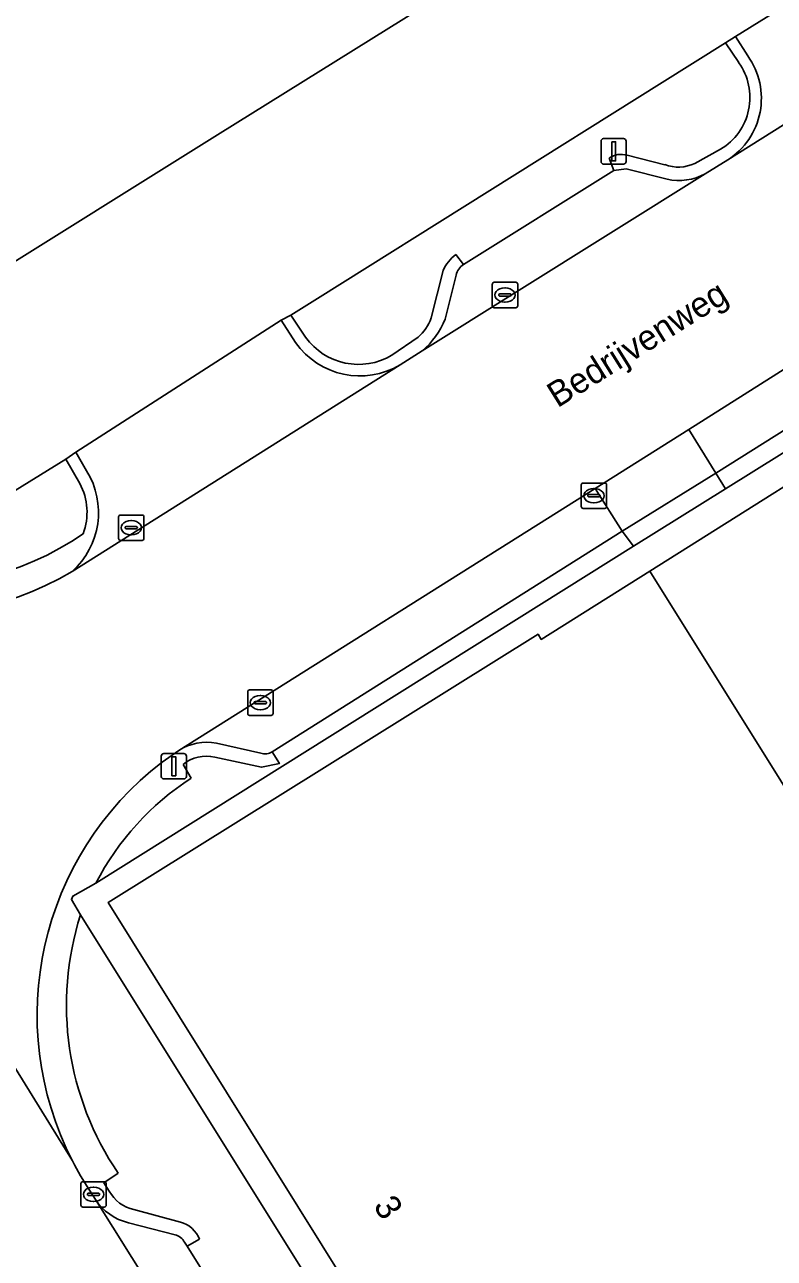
# Model space of a CAD drawing. Extents: x 158455 to 159797, y 387218 to 388672.
# Drawn here: x 158669.4 to 158698.98, y 387821.12 to 387869.77 of the extents above; entities that cross this region are included whole.
import ezdxf

# ---------------------------------------------------------------- set-up
doc = ezdxf.new("R2010")
doc.units = 0
for name, color, linetype in [('IMGEO_Erf', 7, 'Continuous'), ('IMGEO_Kolk', 7, 'Continuous'), ('IMGEO_Lichtmast', 7, 'Continuous'), ('IMGEO_Openbare_ruimte_label', 7, 'Continuous'), ('IMGEO_Pand', 7, 'Continuous'), ('IMGEO_Pand_nummerreeks', 7, 'Continuous'), ('IMGEO_Parkeervlak_open', 7, 'Continuous'), ('IMGEO_Rijbaan_lokaal_gesloten', 7, 'Continuous'), ('IMGEO_Voetpad_open', 7, 'Continuous')]:
    doc.layers.add(name, color=color, linetype=linetype)

msp = doc.modelspace()

# ---------------------------------------------------------------- linework, layer by layer
at = {"layer": 'IMGEO_Erf'}
for points in [[(158744.632, 387907.644), (158716.744, 387890.253), (158714.098, 387894.495), (158687.775, 387878.041), (158690.425, 387873.793), (158677.015, 387865.43), (158667.384, 387859.424), (158662.454, 387856.35), (158644.272, 387885.505), (158643.854, 387886.176), (158641.521, 387884.673), (158641.96, 387883.947), (158641.155, 387883.425), (158643.018, 387880.44), (158642.777, 387880.261), (158649.526, 387869.562), (158649.764, 387869.704), (158660.427, 387852.506)], [(158667.843, 387850.68), (158671.035, 387852.64), (158671.42, 387852.913), (158679.517, 387858.122), (158679.905, 387858.319), (158680.956, 387858.977), (158694.549, 387867.497), (158697.049, 387869.064), (158697.447, 387869.303), (158720.745, 387883.755), (158721.126, 387883.994), (158737.622, 387894.417), (158738.014, 387894.663), (158743.631, 387898.186), (158744.037, 387898.407), (158746.473, 387899.899)], [(158707.009, 387857.672), (158697.055, 387851.465), (158693.417, 387849.212), (158672.211, 387835.913), (158671.304, 387835.407), (158671.246, 387835.269), (158671.606, 387834.665), (158691.111, 387803.48), (158696.218, 387795.316), (158699.252, 387790.473), (158714.054, 387766.818), (158717.252, 387761.719), (158733.714, 387772.034), (158739.37, 387775.529), (158743.923, 387778.371), (158747.2, 387780.372), (158755.504, 387785.603)]]:
    msp.add_lwpolyline(points, dxfattribs=at)
msp.add_lwpolyline([(158694.061, 387848.221), (158704.182, 387854.586), (158709.488, 387846.148), (158713.329, 387848.544), (158722.022, 387834.609), (158708.006, 387825.866), (158703.715, 387823.19), (158703.941, 387822.828), (158691.073, 387814.801), (158693.667, 387810.644), (158689.585, 387808.098), (158672.704, 387835.159), (158689.655, 387845.732), (158689.781, 387845.53)], close=True, dxfattribs=at)
at = {"layer": 'IMGEO_Kolk'}
for p, q in [((158687.853, 387858.688), (158687.853, 387859.54)), ((158687.928, 387859.614), (158688.78, 387859.614)), ((158688.854, 387859.54), (158688.854, 387858.688)), ((158688.112, 387859.108), (158688.112, 387859.12)), ((158688.55, 387859.071), (158688.152, 387859.071)), ((158688.155, 387859.157), (158688.553, 387859.157)), ((158688.341, 387859.394), (158688.366, 387859.394)), ((158688.596, 387859.12), (158688.596, 387859.108)), ((158688.78, 387858.614), (158687.928, 387858.614)), ((158688.364, 387858.834), (158688.339, 387858.834)), ((158691.434, 387851.697), (158692.286, 387851.697)), ((158691.359, 387850.771), (158691.359, 387851.623)), ((158691.618, 387851.191), (158691.618, 387851.203)), ((158691.661, 387851.24), (158692.059, 387851.24)), ((158691.847, 387851.477), (158691.872, 387851.477)), ((158692.102, 387851.203), (158692.102, 387851.191)), ((158692.36, 387851.623), (158692.36, 387850.771)), ((158692.056, 387851.154), (158691.658, 387851.154)), ((158691.87, 387850.917), (158691.845, 387850.917)), ((158673.108, 387849.51), (158673.108, 387850.362)), ((158673.183, 387850.436), (158674.035, 387850.436)), ((158674.109, 387850.362), (158674.109, 387849.51)), ((158692.286, 387850.697), (158691.434, 387850.697)), ((158673.367, 387849.93), (158673.367, 387849.942)), ((158673.805, 387849.893), (158673.407, 387849.893)), ((158673.41, 387849.979), (158673.808, 387849.979)), ((158673.596, 387850.216), (158673.621, 387850.216)), ((158673.851, 387849.942), (158673.851, 387849.93)), ((158674.035, 387849.436), (158673.183, 387849.436)), ((158673.619, 387849.656), (158673.594, 387849.656)), ((158678.203, 387842.611), (158678.203, 387843.463)), ((158678.278, 387843.537), (158679.13, 387843.537)), ((158679.204, 387843.463), (158679.204, 387842.611)), ((158678.462, 387843.031), (158678.462, 387843.043)), ((158678.9, 387842.994), (158678.502, 387842.994)), ((158678.505, 387843.08), (158678.903, 387843.08)), ((158678.691, 387843.317), (158678.716, 387843.317)), ((158678.946, 387843.043), (158678.946, 387843.031)), ((158679.13, 387842.537), (158678.278, 387842.537)), ((158678.714, 387842.757), (158678.689, 387842.757)), ((158671.62, 387823.22), (158671.62, 387824.072)), ((158671.695, 387824.146), (158672.547, 387824.146)), ((158672.621, 387824.072), (158672.621, 387823.22)), ((158671.879, 387823.64), (158671.879, 387823.652)), ((158672.317, 387823.603), (158671.919, 387823.603)), ((158671.922, 387823.689), (158672.32, 387823.689)), ((158672.108, 387823.926), (158672.133, 387823.926)), ((158672.363, 387823.652), (158672.363, 387823.64)), ((158672.547, 387823.146), (158671.695, 387823.146)), ((158672.131, 387823.366), (158672.106, 387823.366))]:
    msp.add_line(p, q, dxfattribs=at)
for points in [[(158687.853, 387858.688), (158687.853, 387859.54)], [(158687.928, 387859.614), (158688.78, 387859.614)], [(158688.854, 387859.54), (158688.854, 387858.688)], [(158688.78, 387858.614), (158687.928, 387858.614)], [(158691.434, 387851.697), (158692.286, 387851.697)], [(158691.359, 387850.771), (158691.359, 387851.623)], [(158692.36, 387851.623), (158692.36, 387850.771)], [(158673.108, 387849.51), (158673.108, 387850.362)], [(158673.183, 387850.436), (158674.035, 387850.436)], [(158674.109, 387850.362), (158674.109, 387849.51)], [(158692.286, 387850.697), (158691.434, 387850.697)], [(158674.035, 387849.436), (158673.183, 387849.436)], [(158678.203, 387842.611), (158678.203, 387843.463)], [(158678.278, 387843.537), (158679.13, 387843.537)], [(158679.204, 387843.463), (158679.204, 387842.611)], [(158679.13, 387842.537), (158678.278, 387842.537)], [(158671.62, 387823.22), (158671.62, 387824.072)], [(158671.695, 387824.146), (158672.547, 387824.146)], [(158672.621, 387824.072), (158672.621, 387823.22)], [(158672.547, 387823.146), (158671.695, 387823.146)]]:
    msp.add_lwpolyline(points, dxfattribs=at)
for centre, radius, start, end in [((158687.93, 387859.538), 0.0765, 91.552, 178.448), ((158687.93, 387859.538), 0.0765, 91.552, 178.448), ((158688.778, 387859.538), 0.0765, 1.552, 88.448), ((158688.778, 387859.538), 0.0765, 1.552, 88.448), ((158688.152, 387859.117), 0.0403, 85.8775, 175.7526), ((158688.149, 387859.107), 0.0366, 178.938, 274.7102), ((158688.553, 387859.114), 0.043, 264.8664, 352.4533), ((158688.557, 387859.119), 0.0386, 1.7309, 96.639), ((158687.93, 387858.69), 0.0765, 181.552, 268.448), ((158687.93, 387858.69), 0.0765, 181.552, 268.448), ((158688.778, 387858.69), 0.0765, 271.552, 358.448), ((158688.778, 387858.69), 0.0765, 271.552, 358.448), ((158691.436, 387851.621), 0.0765, 91.552, 178.448), ((158691.436, 387851.621), 0.0765, 91.552, 178.448), ((158692.284, 387851.621), 0.0765, 1.552, 88.448), ((158692.284, 387851.621), 0.0765, 1.552, 88.448), ((158691.658, 387851.2), 0.0403, 85.8775, 175.7526), ((158692.063, 387851.202), 0.0386, 1.7309, 96.639), ((158691.436, 387850.773), 0.0765, 181.552, 268.448), ((158691.436, 387850.773), 0.0765, 181.552, 268.448), ((158691.655, 387851.19), 0.0366, 178.938, 274.7102), ((158692.059, 387851.197), 0.043, 264.8664, 352.4533), ((158692.284, 387850.773), 0.0765, 271.552, 358.448), ((158692.284, 387850.773), 0.0765, 271.552, 358.448), ((158673.185, 387850.36), 0.0765, 91.552, 178.448), ((158673.185, 387850.36), 0.0765, 91.552, 178.448), ((158674.033, 387850.36), 0.0765, 1.552, 88.448), ((158674.033, 387850.36), 0.0765, 1.552, 88.448), ((158673.407, 387849.939), 0.0403, 85.8775, 175.7526), ((158673.404, 387849.929), 0.0366, 178.938, 274.7102), ((158673.808, 387849.936), 0.043, 264.8664, 352.4533), ((158673.812, 387849.941), 0.0386, 1.7309, 96.639), ((158673.185, 387849.512), 0.0765, 181.552, 268.448), ((158673.185, 387849.512), 0.0765, 181.552, 268.448), ((158674.033, 387849.512), 0.0765, 271.552, 358.448), ((158674.033, 387849.512), 0.0765, 271.552, 358.448), ((158678.28, 387843.461), 0.0765, 91.552, 178.448), ((158678.28, 387843.461), 0.0765, 91.552, 178.448), ((158679.128, 387843.461), 0.0765, 1.552, 88.448), ((158679.128, 387843.461), 0.0765, 1.552, 88.448), ((158678.502, 387843.04), 0.0403, 85.8775, 175.7526), ((158678.499, 387843.03), 0.0366, 178.938, 274.7102), ((158678.903, 387843.037), 0.043, 264.8664, 352.4533), ((158678.907, 387843.042), 0.0386, 1.7309, 96.639), ((158678.28, 387842.613), 0.0765, 181.552, 268.448), ((158678.28, 387842.613), 0.0765, 181.552, 268.448), ((158679.128, 387842.613), 0.0765, 271.552, 358.448), ((158679.128, 387842.613), 0.0765, 271.552, 358.448), ((158671.697, 387824.07), 0.0765, 91.552, 178.448), ((158671.697, 387824.07), 0.0765, 91.552, 178.448), ((158672.545, 387824.07), 0.0765, 1.552, 88.448), ((158672.545, 387824.07), 0.0765, 1.552, 88.448), ((158671.919, 387823.649), 0.0403, 85.8775, 175.7526), ((158671.916, 387823.639), 0.0366, 178.938, 274.7102), ((158672.32, 387823.646), 0.043, 264.8664, 352.4533), ((158672.324, 387823.651), 0.0386, 1.7309, 96.639), ((158671.697, 387823.222), 0.0765, 181.552, 268.448), ((158671.697, 387823.222), 0.0765, 181.552, 268.448), ((158672.545, 387823.222), 0.0765, 271.552, 358.448), ((158672.545, 387823.222), 0.0765, 271.552, 358.448)]:
    msp.add_arc(centre, radius, start, end, dxfattribs=at)
for centre, major_axis, ratio, start_param, end_param in [((158688.34, 387859.114), (-0.387, 0.002), 0.722429, 4.712389, 7.853982), ((158688.365, 387859.114), (-0.39, 0.002), 0.717154, 1.570796, 4.712389), ((158691.846, 387851.197), (-0.387, 0.002), 0.722429, 4.712389, 7.853982), ((158691.871, 387851.197), (-0.39, 0.002), 0.717154, 1.570796, 4.712389), ((158673.595, 387849.936), (-0.387, 0.002), 0.722429, 4.712389, 7.853982), ((158673.62, 387849.936), (-0.39, 0.002), 0.717154, 1.570796, 4.712389), ((158678.69, 387843.037), (-0.387, 0.002), 0.722429, 4.712389, 7.853982), ((158678.715, 387843.037), (-0.39, 0.002), 0.717154, 1.570796, 4.712389), ((158672.107, 387823.646), (-0.387, 0.002), 0.722429, 4.712389, 7.853982), ((158672.132, 387823.646), (-0.39, 0.002), 0.717154, 1.570796, 4.712389)]:
    msp.add_ellipse(centre, major_axis=major_axis, ratio=ratio, start_param=start_param, end_param=end_param, dxfattribs=at)
at = {"layer": 'IMGEO_Lichtmast'}
for p, q in [((158692.144, 387864.38), (158692.144, 387865.18)), ((158692.144, 387865.18), (158692.144, 387864.38)), ((158692.244, 387865.28), (158693.034, 387865.28)), ((158693.034, 387865.28), (158692.244, 387865.28)), ((158693.134, 387865.18), (158693.134, 387864.38)), ((158693.134, 387864.38), (158693.134, 387865.18)), ((158693.034, 387864.28), (158692.244, 387864.28)), ((158692.244, 387864.28), (158693.034, 387864.28)), ((158674.895, 387841.03), (158675.685, 387841.03)), ((158675.685, 387841.03), (158674.895, 387841.03)), ((158674.795, 387840.13), (158674.795, 387840.93)), ((158674.795, 387840.93), (158674.795, 387840.13)), ((158675.785, 387840.93), (158675.785, 387840.13)), ((158675.785, 387840.13), (158675.785, 387840.93)), ((158675.685, 387840.03), (158674.895, 387840.03)), ((158674.895, 387840.03), (158675.685, 387840.03))]:
    msp.add_line(p, q, dxfattribs=at)
for points in [[(158692.564, 387865.155), (158692.714, 387865.155), (158692.714, 387864.405), (158692.564, 387864.405), (158692.564, 387865.155)], [(158675.215, 387840.905), (158675.365, 387840.905), (158675.365, 387840.155), (158675.215, 387840.155), (158675.215, 387840.905)]]:
    msp.add_lwpolyline(points, dxfattribs=at)
for centre, start, end in [((158692.244, 387865.18), 90, 180), ((158692.244, 387865.18), 90, 180), ((158693.034, 387865.18), 0, 90), ((158693.034, 387865.18), 360, 90), ((158692.244, 387864.38), 180, 270), ((158692.244, 387864.38), 180, 270), ((158693.034, 387864.38), 270, 0), ((158693.034, 387864.38), 270, 0), ((158674.895, 387840.93), 90, 180), ((158674.895, 387840.93), 90, 180), ((158675.685, 387840.93), 0, 90), ((158675.685, 387840.93), 360, 90), ((158674.895, 387840.13), 180, 270), ((158674.895, 387840.13), 180, 270), ((158675.685, 387840.13), 270, 0), ((158675.685, 387840.13), 270, 0)]:
    msp.add_arc(centre, 0.1, start, end, dxfattribs=at)
at = {"layer": 'IMGEO_Pand'}
for points in [[(158650.308, 387937.927), (158647.66, 387942.169), (158619.858, 387924.778), (158637.955, 387895.772), (158638.476, 387894.936), (158636.079, 387893.406), (158641.521, 387884.673), (158643.854, 387886.176), (158644.272, 387885.505), (158662.454, 387856.35), (158667.384, 387859.424), (158677.015, 387865.43), (158690.425, 387873.793), (158687.775, 387878.041)], [(158708.006, 387825.866), (158722.022, 387834.609), (158713.329, 387848.544), (158709.488, 387846.148), (158704.182, 387854.586), (158694.061, 387848.221), (158699.23, 387839.95)], [(158708.006, 387825.866), (158699.23, 387839.95), (158694.061, 387848.221), (158689.781, 387845.53), (158689.655, 387845.732), (158672.704, 387835.159), (158689.585, 387808.098), (158693.667, 387810.644), (158691.073, 387814.801), (158703.941, 387822.828), (158703.715, 387823.19)]]:
    msp.add_lwpolyline(points, close=True, dxfattribs=at)
at = {"layer": 'IMGEO_Parkeervlak_open'}
for points in [[(158685.09, 387856.909), (158696.248, 387863.897)], [(158694.748, 387863.678), (158693.129, 387864.089), (158692.648, 387864.022), (158686.714, 387860.312)], [(158704.976, 387859.709), (158705.623, 387860.146), (158695.603, 387853.807), (158696.672, 387852.082), (158703.322, 387856.269), (158703.607, 387856.64), (158704.077, 387858.471)], [(158686.429, 387859.899), (158685.989, 387858.166)], [(158679.173, 387841.095), (158692.978, 387849.807), (158691.905, 387851.479), (158675.481, 387841.157)], [(158676.971, 387841.443), (158678.723, 387841.044)], [(158672.195, 387823.443), (158707.993, 387766.325)], [(158675.335, 387822.05), (158673.495, 387822.526)], [(158711.804, 387763.653), (158711.846, 387763.835), (158711.756, 387764.131), (158711.195, 387765.014), (158696.373, 387788.699), (158693.355, 387793.532), (158688.249, 387801.704), (158675.809, 387821.598), (158675.707, 387821.76)]]:
    msp.add_lwpolyline(points, dxfattribs=at)
for centre, radius, start, end in [((158695.207, 387865.78), 2.151, 257.6751, 298.9379), ((158687.043, 387859.78), 0.625, 121.7289, 169.0541), ((158682.97, 387859.375), 3.253, 310.6852, 338.1705), ((158676.599, 387839.357), 2.119, 79.8905, 121.8406), ((158678.895, 387841.535), 0.52, 250.6725, 302.2594), ((158674.009, 387824.634), 2.17, 213.2947, 256.3082), ((158675.208, 387821.504), 0.561, 27.1885, 76.9337)]:
    msp.add_arc(centre, radius, start, end, dxfattribs=at)
at = {"layer": 'IMGEO_Rijbaan_lokaal_gesloten'}
for points in [[(158748.991, 387897.254), (158748.276, 387896.54), (158747.402, 387895.845), (158737.557, 387889.73), (158736.719, 387889.215), (158726.151, 387882.608), (158724.947, 387881.922), (158697.138, 387864.442), (158696.248, 387863.897), (158685.09, 387856.909), (158684.223, 387856.364), (158671.278, 387848.209)], [(158674.828, 387840.687), (158675.481, 387841.157), (158691.905, 387851.479), (158695.603, 387853.807), (158705.623, 387860.146), (158705.777, 387860.235), (158728.821, 387874.508), (158728.966, 387874.586)], [(158671.29, 387824.964), (158654.921, 387851.458)], [(158654.921, 387851.458), (158671.29, 387824.964)], [(158701.625, 387760.45), (158716.254, 387737.492), (158717.377, 387735.852), (158725.058, 387738.734), (158724.913, 387738.934), (158707.993, 387766.325), (158672.195, 387823.443), (158671.961, 387823.816)]]:
    msp.add_lwpolyline(points, dxfattribs=at)
for centre, radius, start, end in [((158664.921, 387859.002), 12.526, 217.033, 300.4981), ((158682.442, 387830.714), 12.547, 127.3606, 207.2764), ((158682.264, 387830.608), 12.34, 207.2176, 213.3945)]:
    msp.add_arc(centre, radius, start, end, dxfattribs=at)
at = {"layer": 'IMGEO_Voetpad_open'}
for points in [[(158721.157, 387883.073), (158720.745, 387883.755), (158697.447, 387869.303), (158697.93, 387868.543)], [(158697.138, 387864.442), (158724.947, 387881.922)], [(158697.93, 387868.543), (158697.447, 387869.303), (158697.049, 387869.064), (158697.571, 387868.284)], [(158697.571, 387868.284), (158697.049, 387869.064), (158694.549, 387867.497), (158680.956, 387858.977), (158679.905, 387858.319), (158680.484, 387857.449)], [(158696.856, 387864.86), (158695.838, 387864.302)], [(158695.838, 387864.302), (158696.856, 387864.86)], [(158686.411, 387860.71), (158686.714, 387860.312), (158692.648, 387864.022), (158692.468, 387864.513)], [(158692.468, 387864.513), (158692.648, 387864.022), (158693.129, 387864.089), (158694.748, 387863.678)], [(158694.664, 387864.254), (158693.172, 387864.624)], [(158693.172, 387864.624), (158694.664, 387864.254)], [(158696.248, 387863.897), (158697.138, 387864.442)], [(158686.714, 387860.312), (158686.411, 387860.71)], [(158685.439, 387858.211), (158685.909, 387860.078)], [(158685.909, 387860.078), (158685.439, 387858.211)], [(158685.989, 387858.166), (158686.429, 387859.899)], [(158680.09, 387857.237), (158679.517, 387858.122), (158671.42, 387852.913), (158671.85, 387852.177)], [(158680.484, 387857.449), (158679.905, 387858.319), (158679.517, 387858.122), (158680.09, 387857.237)], [(158703.582, 387855.785), (158703.322, 387856.269), (158696.672, 387852.082), (158697.055, 387851.465), (158707.009, 387857.672)], [(158683.892, 387856.736), (158684.922, 387857.45)], [(158684.922, 387857.45), (158683.892, 387856.736)], [(158684.223, 387856.364), (158685.09, 387856.909)], [(158671.278, 387848.209), (158684.223, 387856.364)], [(158671.85, 387852.177), (158671.42, 387852.913), (158671.035, 387852.64), (158671.582, 387851.681)], [(158671.582, 387851.681), (158671.035, 387852.64), (158667.843, 387850.68)], [(158672.211, 387835.913), (158693.417, 387849.212), (158692.978, 387849.807), (158679.173, 387841.095), (158679.453, 387840.633), (158678.753, 387840.492), (158676.907, 387840.891)], [(158675.481, 387841.157), (158674.828, 387840.687)], [(158676.907, 387840.891), (158678.753, 387840.492), (158679.453, 387840.633), (158679.173, 387841.095)], [(158678.723, 387841.044), (158676.971, 387841.443)], [(158675.654, 387840.603), (158675.976, 387840.064)], [(158675.976, 387840.064), (158675.654, 387840.603)], [(158671.606, 387834.665), (158671.246, 387835.269), (158671.304, 387835.407), (158672.211, 387835.913)], [(158676.299, 387821.874), (158675.809, 387821.598), (158688.249, 387801.704), (158691.111, 387803.48), (158671.606, 387834.665)], [(158672.743, 387823.775), (158672.528, 387824.098), (158673.093, 387824.482)], [(158673.093, 387824.482), (158672.528, 387824.098), (158672.743, 387823.775)], [(158671.961, 387823.816), (158672.195, 387823.443)], [(158675.548, 387822.553), (158673.715, 387823.045)], [(158673.715, 387823.045), (158675.548, 387822.553)], [(158673.495, 387822.526), (158675.335, 387822.05)], [(158675.707, 387821.76), (158675.809, 387821.598), (158676.299, 387821.874)]]:
    msp.add_lwpolyline(points, dxfattribs=at)
for points in [[(158691.905, 387851.479), (158692.978, 387849.807), (158696.672, 387852.082), (158695.603, 387853.807)], [(158697.055, 387851.465), (158696.672, 387852.082), (158692.978, 387849.807), (158693.417, 387849.212)]]:
    msp.add_lwpolyline(points, close=True, dxfattribs=at)
for centre, radius, start, end in [((158695.639, 387866.901), 2.376, 300.805, 35.6049), ((158695.639, 387866.901), 2.376, 300.805, 35.6049), ((158695.588, 387866.868), 2.879, 302.5646, 35.5742), ((158695.588, 387866.868), 2.879, 302.5646, 35.5742), ((158692.93, 387863.868), 0.794, 72.2783, 125.6419), ((158692.93, 387863.868), 0.794, 72.2783, 125.6419), ((158695.194, 387865.679), 1.52, 249.6075, 295.0751), ((158695.194, 387865.679), 1.52, 249.6075, 295.0751), ((158695.207, 387865.78), 2.151, 257.6751, 298.9379), ((158687.319, 387859.474), 1.534, 126.287, 156.7925), ((158687.319, 387859.474), 1.534, 126.287, 156.7925), ((158687.043, 387859.78), 0.625, 121.7289, 169.0541), ((158683.741, 387858.808), 1.8, 311.0026, 340.6155), ((158683.741, 387858.808), 1.8, 311.0026, 340.6155), ((158682.97, 387859.375), 3.253, 310.6852, 338.1705), ((158682.629, 387859.037), 3.113, 215.3406, 300.8052), ((158682.629, 387859.037), 3.113, 215.3406, 300.8052), ((158682.579, 387858.96), 2.583, 215.8112, 300.5556), ((158682.579, 387858.96), 2.583, 215.8112, 300.5556), ((158669.195, 387850.535), 3.122, 311.8536, 31.7406), ((158669.195, 387850.535), 3.122, 311.8536, 31.7406), ((158665.062, 387859.371), 11.736, 220.9091, 304.5221), ((158665.062, 387859.371), 11.736, 220.9091, 304.5221), ((158664.921, 387859.002), 12.526, 217.033, 300.4981), ((158669.425, 387850.544), 2.439, 339.7771, 27.7934), ((158669.425, 387850.544), 2.439, 339.7771, 27.7934), ((158676.599, 387839.357), 2.119, 79.8905, 121.8406), ((158678.895, 387841.535), 0.52, 250.6725, 302.2594), ((158682.442, 387830.714), 12.547, 127.3606, 207.2764), ((158676.58, 387839.445), 1.482, 77.2432, 128.6458), ((158676.58, 387839.445), 1.482, 77.2432, 128.6458), ((158681.918, 387830.891), 10.929, 122.9365, 152.6468), ((158681.918, 387830.891), 10.929, 122.9365, 152.6468), ((158682.827, 387831.104), 11.773, 162.3915, 214.2246), ((158682.827, 387831.104), 11.773, 162.3915, 214.2246), ((158682.264, 387830.608), 12.34, 207.2176, 213.3945), ((158674.034, 387824.481), 1.471, 208.6944, 257.4904), ((158674.034, 387824.481), 1.471, 208.6944, 257.4904), ((158674.009, 387824.634), 2.17, 213.2947, 256.3082), ((158675.267, 387821.488), 1.102, 20.5257, 75.2391), ((158675.267, 387821.488), 1.102, 20.5257, 75.2391), ((158675.208, 387821.504), 0.561, 27.1885, 76.9337)]:
    msp.add_arc(centre, radius, start, end, dxfattribs=at)

# ---------------------------------------------------------------- texts
at = {"layer": 'IMGEO_Openbare_ruimte_label'}
msp.add_text('Bedrijvenweg', height=1, rotation=32.0054, dxfattribs=at).set_placement((158690.424, 387854.644))
at = {"layer": 'IMGEO_Pand_nummerreeks'}
msp.add_text('3', height=1, rotation=301.9564, dxfattribs=at).set_placement((158683.137, 387823.196))

doc.saveas('drawing.dxf')
